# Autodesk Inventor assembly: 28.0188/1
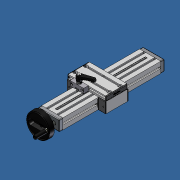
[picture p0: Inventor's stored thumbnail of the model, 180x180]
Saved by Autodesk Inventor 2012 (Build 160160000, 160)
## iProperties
Created: 2007-06
Part Number: 28.0188/1
Document SubType Name: Assembly
Designer: Andy Moles
Description: ADJUSTING UNIT VEN 45X90 F WITH TOP CLAMP
Author: Andy Moles
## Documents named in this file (20)
- C:\Andys Backup Data\ANDY'S INVENTOR\INVENTOR LIBRARIES\PARTS LIBRARY\READY FOR USE MODULES LG\28.0188_1 ADJUSTING UNIT VEN 45X90 F WITH TOP CLAMP.iam
- C:\Andys Backup Data\ANDY'S INVENTOR\INVENTOR LIBRARIES\PARTS LIBRARY\READY FOR USE MODULES LG\SUBCOMPONENTS\28.0200 BEARING PLATE 45X90 HANDWHEEL SIDE.ipt
- C:\Andys Backup Data\ANDY'S INVENTOR\INVENTOR LIBRARIES\PARTS LIBRARY\READY FOR USE MODULES LG\SUBCOMPONENTS\50.1264 BALL BEARING 10X30X9 6200 2RS DIN 625.ipt
- C:\Andys Backup Data\ANDY'S INVENTOR\INVENTOR LIBRARIES\PARTS LIBRARY\READY FOR USE MODULES LG\SUBCOMPONENTS\28.0201 BEARING PLATE 45X90 IDLER SIDE.ipt
- C:\Andys Backup Data\ANDY'S INVENTOR\INVENTOR LIBRARIES\PARTS LIBRARY\READY FOR USE MODULES LG\SUBCOMPONENTS\28.0204 HANDWHEEL 100mm.iam
- C:\Andys Backup Data\ANDY'S INVENTOR\INVENTOR LIBRARIES\PARTS LIBRARY\FASTENING ELEMENTS\NUTS\21.1351 M8 SQUARE NUT.ipt
- C:\Andys Backup Data\ANDY'S INVENTOR\INVENTOR LIBRARIES\PARTS LIBRARY\FASTENING ELEMENTS\SCREWS CAP\21.1204 M8X25.ipt
- C:\Andys Backup Data\ANDY'S INVENTOR\INVENTOR LIBRARIES\PARTS LIBRARY\READY FOR USE MODULES LG\SUBCOMPONENTS\28.0215_3 45x90F  PROFILE FOR TOP LOCK.ipt
- C:\Andys Backup Data\ANDY'S INVENTOR\INVENTOR LIBRARIES\PARTS LIBRARY\READY FOR USE MODULES LG\SUBCOMPONENTS\28.0221_1 ACME SCREW 16X4 TOP LOCK.ipt
- C:\Andys Backup Data\ANDY'S INVENTOR\INVENTOR LIBRARIES\PARTS LIBRARY\FASTENING ELEMENTS\WASHERS\21.1326 DISC SPRING 20.ipt
- C:\Andys Backup Data\ANDY'S INVENTOR\INVENTOR LIBRARIES\PARTS LIBRARY\READY FOR USE MODULES LG\SUBCOMPONENTS\28.0224_1 LWN 32X45-90 90X19-NSC.ipt
- C:\Andys Backup Data\ANDY'S INVENTOR\INVENTOR LIBRARIES\PARTS LIBRARY\READY FOR USE MODULES LG\SUBCOMPONENTS\28.0254 NUT SLIDE CONNECTOR 16.ipt
- C:\Andys Backup Data\ANDY'S INVENTOR\INVENTOR LIBRARIES\PARTS LIBRARY\END CAPS\22.1003_1 END CAP 45x32 Z Gray.iam
- C:\Andys Backup Data\ANDY'S INVENTOR\INVENTOR LIBRARIES\PARTS LIBRARY\COMPONENTS LG\22.1095 SLIDE RAIL LN.iam
- C:\Andys Backup Data\ANDY'S INVENTOR\INVENTOR LIBRARIES\PARTS LIBRARY\READY FOR USE MODULES LG\SUBCOMPONENTS\28.0126 SLIDE 45X32.ipt
- C:\Andys Backup Data\ANDY'S INVENTOR\INVENTOR LIBRARIES\PARTS LIBRARY\END CAPS\22.1014_1 END CAP 90X19 GRAY.ipt
- C:\Andys Backup Data\ANDY'S INVENTOR\INVENTOR LIBRARIES\PARTS LIBRARY\FASTENING ELEMENTS\SCREWS CAP\21.1235 M5X16.ipt
- C:\Andys Backup Data\ANDY'S INVENTOR\INVENTOR LIBRARIES\PARTS LIBRARY\FASTENING ELEMENTS\SCREWS CAP\21.1200 M8X16.ipt
- C:\Andys Backup Data\ANDY'S INVENTOR\INVENTOR LIBRARIES\PARTS LIBRARY\READY FOR USE MODULES LG\SUBCOMPONENTS\28.0257 BRONZE NUT 16X4 NOTCHED.ipt
- C:\Andys Backup Data\ANDY'S INVENTOR\INVENTOR LIBRARIES\PARTS LIBRARY\COMPONENTS LR\28.0270_9 SLIDE CLAMPING UNIT 5mm OFFSET..iam
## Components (37 placed, 19 different names)
1. 28.0215_3 45x90F  PROFILE FOR TOP LOCK:1 — Flush:1, Flush:2, Mate:1, Mate:4, Flush:9, Flush:10, Flush:11, Mate:10, Flush:12, Mate:30, Mate:32
2. 28.0200 BEARING PLATE 45X90 HANDWHEEL SIDE:1 — Insert:4, Insert:6, Insert:7, Insert:11, Flush:10, Mate:10, Flush:12
3. 50.1264 10X30X9 6200 2RS DIN 625 BALL BEARING:1 — Insert:11, Insert:14
4. 50.1264 10X30X9 6200 2RS DIN 625 BALL BEARING:2 — Insert:10
5. 28.0201 BEARING PLATE 45X90 IDLER SIDE:1 — Mate:4, Insert:8, Insert:9, Insert:10, Flush:9, Flush:11
6. 28.0204 HANDWHEEL 100mm:1 [sub-assembly] — Insert:4, Angle:1
7. 21.1204  M8 x 25:1 — Insert:7
8. 21.1204  M8 x 25:2 — Insert:6
9. 21.1204  M8 x 25:3 — Insert:8
10. 21.1204  M8 x 25:4 — Insert:9
11. 28.0221_1 ACME SCREW 16X4 TOP LOCK:1 — Insert:12, Insert:13, Angle:1, Mate:31
12. 21.1326 DISC SPRING 20:1 — Insert:12
13. 21.1326 DISC SPRING 20:2 — Insert:13, Insert:14
14. 28.0254 NUT SLIDE CONNECTOR 16:1 — Insert:15, Angle:2, Mate:24, Angle:7
15. 22.1003\1 END CAP 45x32 Z Gray:1 [sub-assembly] — Insert:29, Angle:8
16. 22.1095 SLIDE RAIL LN:1 [sub-assembly] — Mate:22, Flush:16, Mate:23, Mate:30
17. 28.0126 SLIDE 45X32:1 — Mate:18, Flush:14, Mate:19, Mate:22, Flush:16, Mate:23, Insert:26, Insert:29, Angle:8, Angle:11
18. 22.1014_1 END CAP 90X19 GRAY:1 — Mate:26, Flush:19, Flush:20
19. 28.0224_1 LWN 32X45-90 90X19-NSC:2 — Insert:15, Angle:2, Insert:16, Insert:17, Insert:18, Insert:19, Insert:20, Insert:21, Insert:22, Insert:23, Angle:3, Angle:4, Insert:24, Insert:25, Angle:5, Angle:6, Mate:16, Flush:13, Mate:18, Flush:14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
20. 22.1003\1 END CAP 45x32 Z Gray:2 [sub-assembly] — Insert:28, Angle:9
21. 22.1014_1 END CAP 90X19 GRAY:2 — Mate:25, Flush:17, Flush:18
22. 28.0126 SLIDE 45X32:2 — Mate:16, Flush:13, Mate:17, Mate:20, Flush:15, Mate:21, Insert:27, Insert:28, Angle:9, Angle:10
23. 22.1003\1 END CAP 45x32 Z Gray:3 [sub-assembly] — Insert:27, Angle:10
24. 22.1003\1 END CAP 45x32 Z Gray:4 [sub-assembly] — Insert:26, Angle:11
25. 22.1095 SLIDE RAIL LN:2 [sub-assembly] — Mate:20, Flush:15, Mate:21, Mate:32
26. 21.1235  M5 x 16:1 — Insert:21
27. 21.1235  M5 x 16:2 — Insert:20
28. 21.1200 M8 x 16:1 — Insert:16, Mate:17
29. 21.1200 M8 x 16:2 — Insert:17
30. 21.1200 M8 x 16:3 — Insert:19
31. 21.1200 M8 x 16:4 — Insert:18, Mate:19
32. 28.0257 BRONZE NUT 16X4 NOTCHED:1 — Mate:24, Angle:7, Mate:31
33. 21.1351 M8 SQUARE NUT:2 — Insert:22, Angle:3
34. 21.1351 M8 SQUARE NUT:3 — Insert:23, Angle:4
35. 21.1351 M8 SQUARE NUT:4 — Insert:24, Angle:5
36. 21.1351 M8 SQUARE NUT:5 — Insert:25, Angle:6
37. 28.0270_9 SLIDE CLAMPING UNIT 5mm OFFSET.:1 [sub-assembly] — Mate:27, Mate:28, Mate:29
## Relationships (70: Insert 25, Mate 20, Flush 14, Angle 11)
- Flush:1: 28.0215_3 45x90F  PROFILE FOR TOP LOCK:1
- Flush:2: 28.0215_3 45x90F  PROFILE FOR TOP LOCK:1
- Mate:1: 28.0215_3 45x90F  PROFILE FOR TOP LOCK:1
- Mate:4: 28.0215_3 45x90F  PROFILE FOR TOP LOCK:1 ↔ 28.0201 BEARING PLATE 45X90 IDLER SIDE:1
- Insert:4: 28.0200 BEARING PLATE 45X90 HANDWHEEL SIDE:1 ↔ 28.0204 HANDWHEEL 100mm:1
- Insert:6: 28.0200 BEARING PLATE 45X90 HANDWHEEL SIDE:1 ↔ 21.1204  M8 x 25:2
- Insert:7: 28.0200 BEARING PLATE 45X90 HANDWHEEL SIDE:1 ↔ 21.1204  M8 x 25:1
- Insert:8: 28.0201 BEARING PLATE 45X90 IDLER SIDE:1 ↔ 21.1204  M8 x 25:3
- Insert:9: 28.0201 BEARING PLATE 45X90 IDLER SIDE:1 ↔ 21.1204  M8 x 25:4
- Insert:10: 50.1264 10X30X9 6200 2RS DIN 625 BALL BEARING:2 ↔ 28.0201 BEARING PLATE 45X90 IDLER SIDE:1
- Insert:11: 28.0200 BEARING PLATE 45X90 HANDWHEEL SIDE:1 ↔ 50.1264 10X30X9 6200 2RS DIN 625 BALL BEARING:1
- Flush:9: 28.0215_3 45x90F  PROFILE FOR TOP LOCK:1 ↔ 28.0201 BEARING PLATE 45X90 IDLER SIDE:1
- Flush:10: 28.0215_3 45x90F  PROFILE FOR TOP LOCK:1 ↔ 28.0200 BEARING PLATE 45X90 HANDWHEEL SIDE:1
- Flush:11: 28.0215_3 45x90F  PROFILE FOR TOP LOCK:1 ↔ 28.0201 BEARING PLATE 45X90 IDLER SIDE:1
- Mate:10: 28.0215_3 45x90F  PROFILE FOR TOP LOCK:1 ↔ 28.0200 BEARING PLATE 45X90 HANDWHEEL SIDE:1
- Flush:12: 28.0215_3 45x90F  PROFILE FOR TOP LOCK:1 ↔ 28.0200 BEARING PLATE 45X90 HANDWHEEL SIDE:1
- Insert:12: 28.0221_1 ACME SCREW 16X4 TOP LOCK:1 ↔ 21.1326 DISC SPRING 20:1
- Insert:13: 28.0221_1 ACME SCREW 16X4 TOP LOCK:1 ↔ 21.1326 DISC SPRING 20:2
- Insert:14: 50.1264 10X30X9 6200 2RS DIN 625 BALL BEARING:1 ↔ 21.1326 DISC SPRING 20:2
- Angle:1: 28.0204 HANDWHEEL 100mm:1 ↔ 28.0221_1 ACME SCREW 16X4 TOP LOCK:1
- Insert:15: 28.0254 NUT SLIDE CONNECTOR 16:1 ↔ 28.0224_1 LWN 32X45-90 90X19-NSC:2
- Angle:2: 28.0254 NUT SLIDE CONNECTOR 16:1 ↔ 28.0224_1 LWN 32X45-90 90X19-NSC:2
- Insert:16: 28.0224_1 LWN 32X45-90 90X19-NSC:2 ↔ 21.1200 M8 x 16:1
- Insert:17: 28.0224_1 LWN 32X45-90 90X19-NSC:2 ↔ 21.1200 M8 x 16:2
- Insert:18: 28.0224_1 LWN 32X45-90 90X19-NSC:2 ↔ 21.1200 M8 x 16:4
- Insert:19: 28.0224_1 LWN 32X45-90 90X19-NSC:2 ↔ 21.1200 M8 x 16:3
- Insert:20: 28.0224_1 LWN 32X45-90 90X19-NSC:2 ↔ 21.1235  M5 x 16:2
- Insert:21: 28.0224_1 LWN 32X45-90 90X19-NSC:2 ↔ 21.1235  M5 x 16:1
- Insert:22: 28.0224_1 LWN 32X45-90 90X19-NSC:2 ↔ 21.1351 M8 SQUARE NUT:2
- Insert:23: 28.0224_1 LWN 32X45-90 90X19-NSC:2 ↔ 21.1351 M8 SQUARE NUT:3
- Angle:3: 28.0224_1 LWN 32X45-90 90X19-NSC:2 ↔ 21.1351 M8 SQUARE NUT:2
- Angle:4: 28.0224_1 LWN 32X45-90 90X19-NSC:2 ↔ 21.1351 M8 SQUARE NUT:3
- Insert:24: 28.0224_1 LWN 32X45-90 90X19-NSC:2 ↔ 21.1351 M8 SQUARE NUT:4
- Insert:25: 28.0224_1 LWN 32X45-90 90X19-NSC:2 ↔ 21.1351 M8 SQUARE NUT:5
- Angle:5: 28.0224_1 LWN 32X45-90 90X19-NSC:2 ↔ 21.1351 M8 SQUARE NUT:4
- Angle:6: 28.0224_1 LWN 32X45-90 90X19-NSC:2 ↔ 21.1351 M8 SQUARE NUT:5
- Mate:16: 28.0224_1 LWN 32X45-90 90X19-NSC:2 ↔ 28.0126 SLIDE 45X32:2
- Flush:13: 28.0224_1 LWN 32X45-90 90X19-NSC:2 ↔ 28.0126 SLIDE 45X32:2
- Mate:17: 28.0126 SLIDE 45X32:2 ↔ 21.1200 M8 x 16:1
- Mate:18: 28.0126 SLIDE 45X32:1 ↔ 28.0224_1 LWN 32X45-90 90X19-NSC:2
- Flush:14: 28.0126 SLIDE 45X32:1 ↔ 28.0224_1 LWN 32X45-90 90X19-NSC:2
- Mate:19: 28.0126 SLIDE 45X32:1 ↔ 21.1200 M8 x 16:4
- Mate:20: 28.0126 SLIDE 45X32:2 ↔ 22.1095 SLIDE RAIL LN:2
- Flush:15: 28.0126 SLIDE 45X32:2 ↔ 22.1095 SLIDE RAIL LN:2
- Mate:21: 28.0126 SLIDE 45X32:2 ↔ 22.1095 SLIDE RAIL LN:2
- Mate:22: 22.1095 SLIDE RAIL LN:1 ↔ 28.0126 SLIDE 45X32:1
- Flush:16: 22.1095 SLIDE RAIL LN:1 ↔ 28.0126 SLIDE 45X32:1
- Mate:23: 22.1095 SLIDE RAIL LN:1 ↔ 28.0126 SLIDE 45X32:1
- Mate:24: 28.0254 NUT SLIDE CONNECTOR 16:1 ↔ 28.0257 BRONZE NUT 16X4 NOTCHED:1
- Angle:7: 28.0254 NUT SLIDE CONNECTOR 16:1 ↔ 28.0257 BRONZE NUT 16X4 NOTCHED:1
- Insert:26: 28.0126 SLIDE 45X32:1 ↔ 22.1003\1 END CAP 45x32 Z Gray:4
- Insert:27: 28.0126 SLIDE 45X32:2 ↔ 22.1003\1 END CAP 45x32 Z Gray:3
- Insert:28: 22.1003\1 END CAP 45x32 Z Gray:2 ↔ 28.0126 SLIDE 45X32:2
- Insert:29: 22.1003\1 END CAP 45x32 Z Gray:1 ↔ 28.0126 SLIDE 45X32:1
- Angle:8: 22.1003\1 END CAP 45x32 Z Gray:1 ↔ 28.0126 SLIDE 45X32:1
- Angle:9: 22.1003\1 END CAP 45x32 Z Gray:2 ↔ 28.0126 SLIDE 45X32:2
- Angle:10: 28.0126 SLIDE 45X32:2 ↔ 22.1003\1 END CAP 45x32 Z Gray:3
- Angle:11: 28.0126 SLIDE 45X32:1 ↔ 22.1003\1 END CAP 45x32 Z Gray:4
- Mate:25: 28.0224_1 LWN 32X45-90 90X19-NSC:2 ↔ 22.1014_1 END CAP 90X19 GRAY:2
- Flush:17: 28.0224_1 LWN 32X45-90 90X19-NSC:2 ↔ 22.1014_1 END CAP 90X19 GRAY:2
- Flush:18: 28.0224_1 LWN 32X45-90 90X19-NSC:2 ↔ 22.1014_1 END CAP 90X19 GRAY:2
- Mate:26: 22.1014_1 END CAP 90X19 GRAY:1 ↔ 28.0224_1 LWN 32X45-90 90X19-NSC:2
- Flush:19: 22.1014_1 END CAP 90X19 GRAY:1 ↔ 28.0224_1 LWN 32X45-90 90X19-NSC:2
- Flush:20: 22.1014_1 END CAP 90X19 GRAY:1 ↔ 28.0224_1 LWN 32X45-90 90X19-NSC:2
- Mate:27: 28.0224_1 LWN 32X45-90 90X19-NSC:2 ↔ 28.0270_9 SLIDE CLAMPING UNIT 5mm OFFSET.:1
- Mate:28: 28.0224_1 LWN 32X45-90 90X19-NSC:2 ↔ 28.0270_9 SLIDE CLAMPING UNIT 5mm OFFSET.:1
- Mate:29: 28.0224_1 LWN 32X45-90 90X19-NSC:2 ↔ 28.0270_9 SLIDE CLAMPING UNIT 5mm OFFSET.:1
- Mate:30: 28.0215_3 45x90F  PROFILE FOR TOP LOCK:1 ↔ 22.1095 SLIDE RAIL LN:1
- Mate:31: 28.0221_1 ACME SCREW 16X4 TOP LOCK:1 ↔ 28.0257 BRONZE NUT 16X4 NOTCHED:1
- Mate:32: 28.0215_3 45x90F  PROFILE FOR TOP LOCK:1 ↔ 22.1095 SLIDE RAIL LN:2
